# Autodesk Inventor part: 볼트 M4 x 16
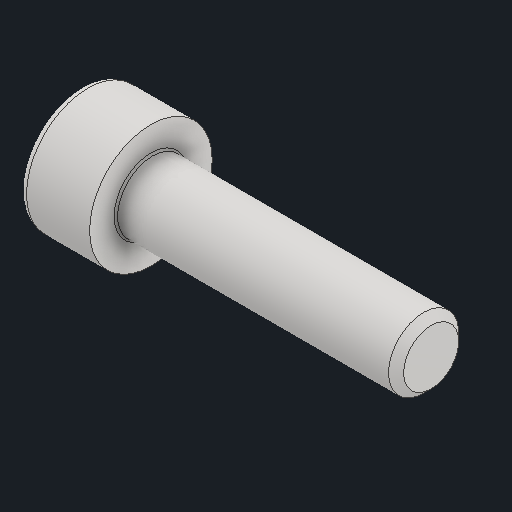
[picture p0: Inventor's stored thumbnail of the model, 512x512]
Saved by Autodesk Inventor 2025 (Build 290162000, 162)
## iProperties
Created: 2025-08
Part Number: 볼트 M4 x 16
Material: 스테인리스강
Description: 6각 소켓 머리 캡 나사
Document SubType Name: Modeling
Designer: infra023
Density: 8.08 g/cm^3
Appearance: 기본값
Author: jhkim
Sending System: Autodesk Inventor 2026
Preprocessor: ST-DEVELOPER v20.1
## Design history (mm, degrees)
feature "Solid1"
node "솔리드1"
